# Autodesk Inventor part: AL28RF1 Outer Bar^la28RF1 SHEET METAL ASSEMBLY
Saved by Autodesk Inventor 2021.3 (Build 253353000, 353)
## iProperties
Created: 2023-01
Part Number: AL28RF1 Outer Bar^la28RF1 SHEET METAL ASSEMBLY
Material: Generic
Document SubType Name: Modeling
Designer: AdminForWorker
Density: 1 g/cm^3
Appearance: Default
Title: AL28RF1 Outer Bar^la28RF1 SHEET METAL ASSEMBLY
Author: AdminForWorker
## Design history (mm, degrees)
feature "Cut-Extrude2"
body "Solid1"
